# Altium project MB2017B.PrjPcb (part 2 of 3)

## Sheet Power_Stage.SchDoc: Power Stage
size A2; Date: Not used; ApprovedBy: Not used; CheckedBy: Not used; Author: Not used; CompanyName: STMicroelectronics; DrawnBy: Not used; Engineer: Not used; Organization: Not used; Address1: Not used; Address2: Not used; Address3: Not used; Address4: Not used; DocumentNumber: Not used; Revision: Not used; SheetNumber: 3; SheetTotal: 7
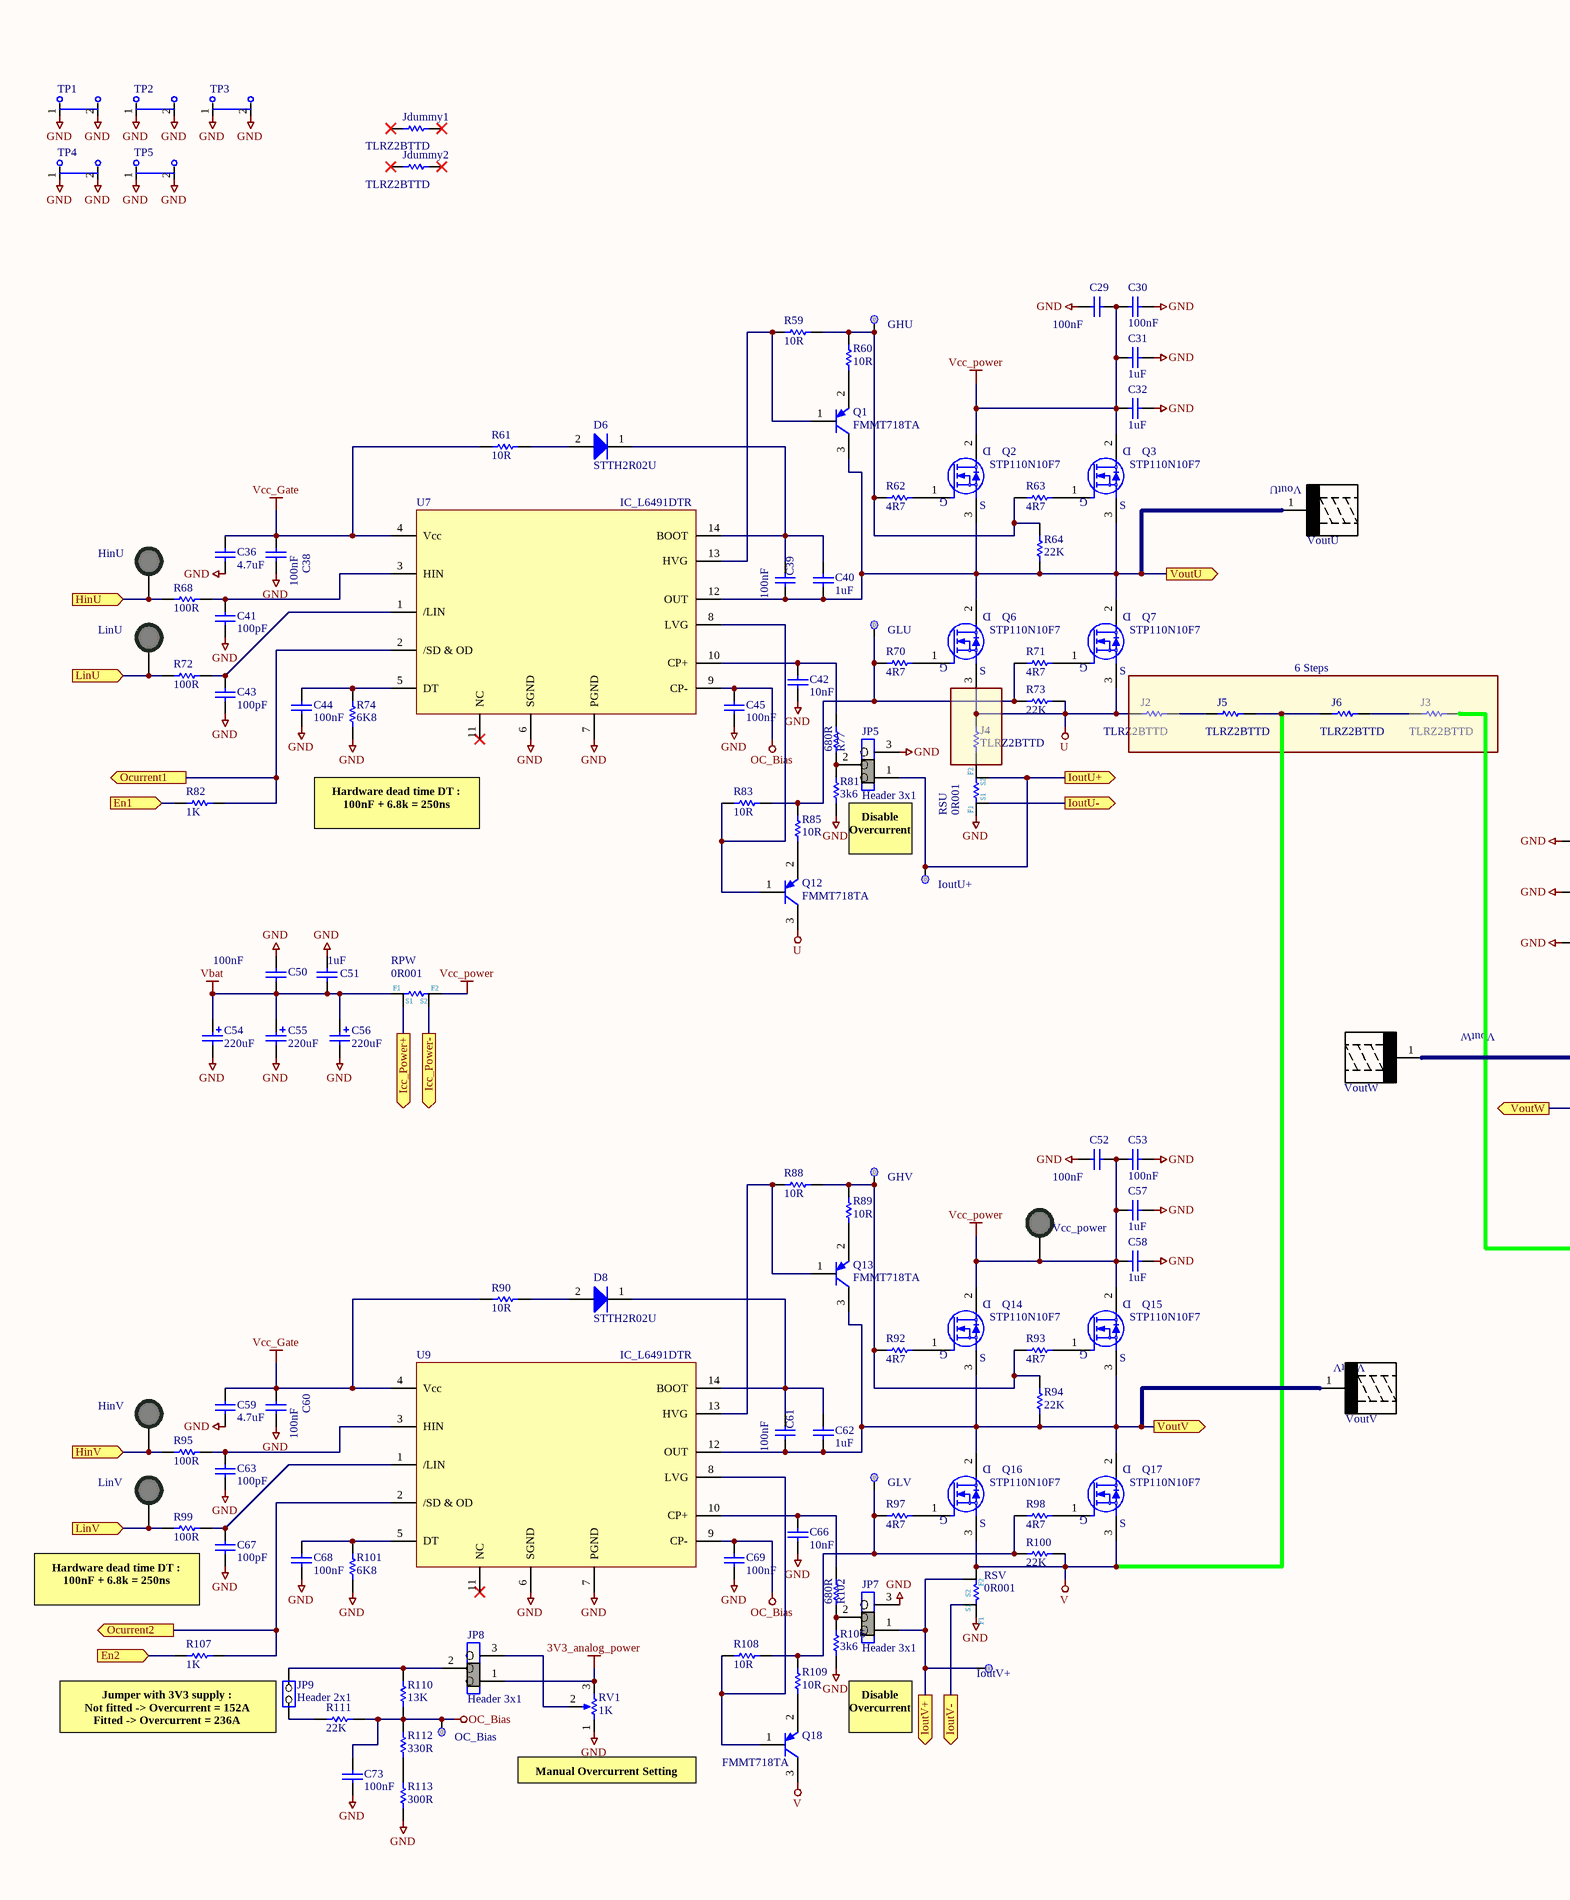
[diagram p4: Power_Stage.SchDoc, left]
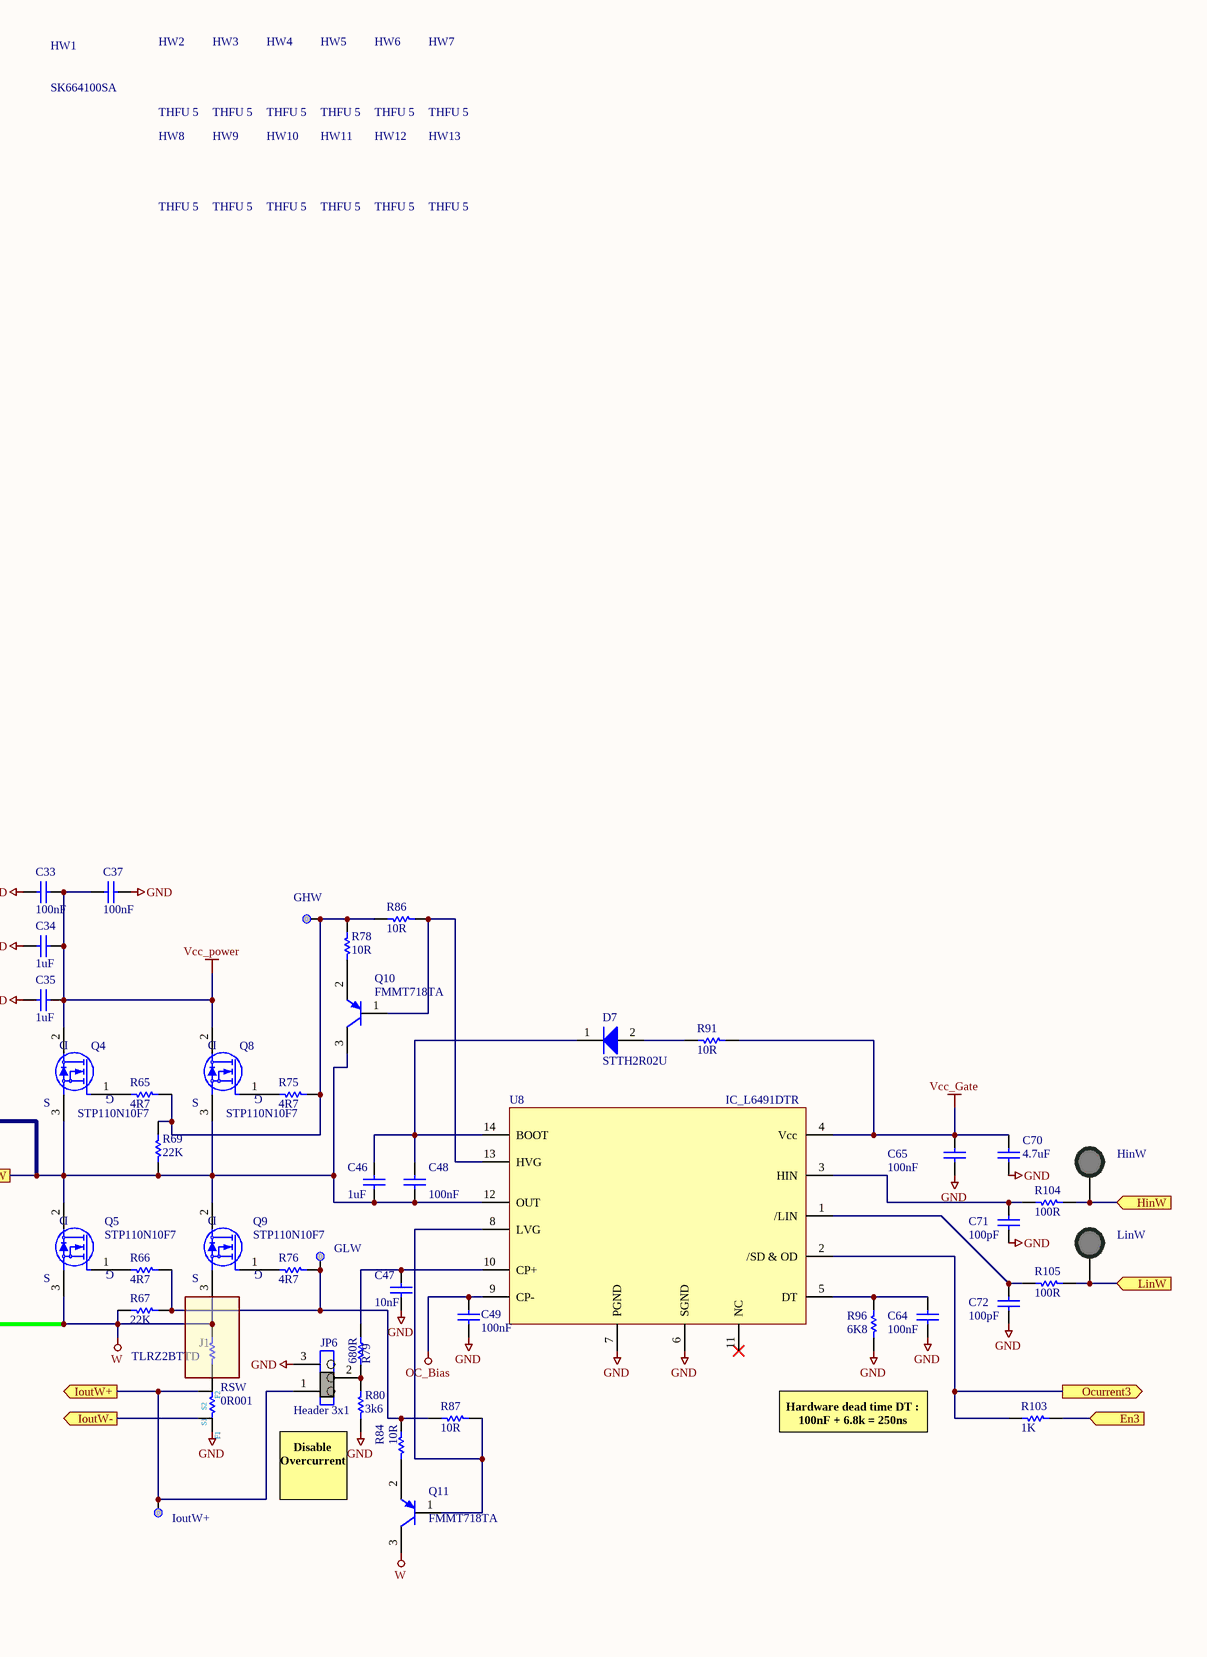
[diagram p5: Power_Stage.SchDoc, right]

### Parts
C29  value 100nF  [C0805]  (hidden comment: Capacitor)
C30  value 100nF  [C0805]  (hidden comment: Capacitor)
C31  value 1uF  [C1206_H1P6]  (hidden comment: Capacitor)
C32  value 1uF  [C1206_H1P6]  (hidden comment: Capacitor)
C33  value 100nF  [C0805]  (hidden comment: Capacitor)
C34  value 1uF  [C1206_H1P6]  (hidden comment: Capacitor)
C35  value 1uF  [C1206_H1P6]  (hidden comment: Capacitor)
C36  value 4.7uF  [C1206_H1P25]  (hidden comment: Capacitor)
C37  value 100nF  [C0805]  (hidden comment: Capacitor)
C38  value 100nF  [C0805_H0P85]  (hidden comment: Capacitor)
C39  value 100nF  [C0805_H0P85]  (hidden comment: Capacitor)
C40  value 1uF  [C1206_H1P15]  (hidden comment: Capacitor)
C41  value 100pF  [C0603_H0P8]  (hidden comment: Capacitor)
C42  value 10nF  [C0603]  (hidden comment: Capacitor)
C43  value 100pF  [C0603_H0P8]  (hidden comment: Capacitor)
C44  value 100nF  [C0603]  (hidden comment: Capacitor)
C45  value 100nF  [C0603]  (hidden comment: Capacitor)
C46  value 1uF  [C1206_H1P15]  (hidden comment: Capacitor)
C47  value 10nF  [C0603]  (hidden comment: Capacitor)
C48  value 100nF  [C0805_H0P85]  (hidden comment: Capacitor)
C49  value 100nF  [C0603]  (hidden comment: Capacitor)
C50  value 100nF  [C0805]  (hidden comment: Capacitor)
C51  value 1uF  [C1206_H1P6]  (hidden comment: Capacitor)
C52  value 100nF  [C0805]  (hidden comment: Capacitor)
C53  value 100nF  [C0805]  (hidden comment: Capacitor)
C54  value 220uF  [CPOL_TDK_B41858C9227M000_H25]  (hidden comment: Cap_POL_TANA)
C55  value 220uF  [CPOL_TDK_B41858C9227M000_H25]  (hidden comment: Cap_POL_TANA)
C56  value 220uF  [CPOL_TDK_B41858C9227M000_H25]  (hidden comment: Cap_POL_TANA)
C57  value 1uF  [C1206_H1P6]  (hidden comment: Capacitor)
C58  value 1uF  [C1206_H1P6]  (hidden comment: Capacitor)
C59  value 4.7uF  [C1206_H1P25]  (hidden comment: Capacitor)
C60  value 100nF  [C0805_H0P85]  (hidden comment: Capacitor)
C61  value 100nF  [C0805_H0P85]  (hidden comment: Capacitor)
C62  value 1uF  [C1206_H1P15]  (hidden comment: Capacitor)
C63  value 100pF  [C0603_H0P8]  (hidden comment: Capacitor)
C64  value 100nF  [C0603]  (hidden comment: Capacitor)
C65  value 100nF  [C0805_H0P85]  (hidden comment: Capacitor)
C66  value 10nF  [C0603]  (hidden comment: Capacitor)
C67  value 100pF  [C0603_H0P8]  (hidden comment: Capacitor)
C68  value 100nF  [C0603]  (hidden comment: Capacitor)
C69  value 100nF  [C0603]  (hidden comment: Capacitor)
C70  value 4.7uF  [C1206_H1P25]  (hidden comment: Capacitor)
C71  value 100pF  [C0603_H0P8]  (hidden comment: Capacitor)
C72  value 100pF  [C0603_H0P8]  (hidden comment: Capacitor)
C73  value 100nF  [C0603]  (hidden comment: Capacitor)
D6  value STTH2R02U  [DIO_SMB_1K_2A]  (hidden comment: DIODE_1K_2A)
D7  value STTH2R02U  [DIO_SMB_1K_2A]  (hidden comment: DIODE_1K_2A)
D8  value STTH2R02U  [DIO_SMB_1K_2A]  (hidden comment: DIODE_1K_2A)
GHU  Test Point  [TP_SMD_1MM]  (value not drawn)  (no BOM)
GHV  Test Point  [TP_SMD_1MM]  (value not drawn)  (no BOM)
GHW  Test Point  [TP_SMD_1MM]  (value not drawn)  (no BOM)
GLU  Test Point  [TP_SMD_1MM]  (value not drawn)  (no BOM)
GLV  Test Point  [TP_SMD_1MM]  (value not drawn)  (no BOM)
GLW  Test Point  [TP_SMD_1MM]  (value not drawn)  (no BOM)
HinU  Test_pin_conn_black - NOT CONNECTED  [TP_PTH-1P02MM_TEST-TERMINAL_RS_101-2391_BLACK]  (value not drawn)
HinV  Test_pin_conn_black - NOT CONNECTED  [TP_PTH-1P02MM_TEST-TERMINAL_RS_101-2391_BLACK]  (value not drawn)
HinW  Test_pin_conn_black - NOT CONNECTED  [TP_PTH-1P02MM_TEST-TERMINAL_RS_101-2391_BLACK]  (value not drawn)
HW1  SK664100SA  [MISC_Fischer_Elektronik_SK664100SA]
HW2  THFU 5
HW3  THFU 5
HW4  THFU 5
HW5  THFU 5
HW6  THFU 5
HW7  THFU 5
HW8  THFU 5
HW9  THFU 5
HW10  THFU 5
HW11  THFU 5
HW12  THFU 5
HW13  THFU 5
IoutU+  Test Point  [TP_SMD_1MM]  (value not drawn)  (no BOM)
IoutV+  Test Point  [TP_SMD_1MM]  (value not drawn)  (no BOM)
IoutW+  Test Point  [TP_SMD_1MM]  (value not drawn)  (no BOM)
J1  value TLRZ2BTTD  [MISC_JUMPER_1206_H0P55]  (hidden comment: Resistor)
J2  value TLRZ2BTTD  [MISC_JUMPER_1206_H0P55]  (hidden comment: Resistor)
J3  value TLRZ2BTTD  [MISC_JUMPER_1206_H0P55]  (hidden comment: Resistor)
J4  value TLRZ2BTTD  [MISC_JUMPER_1206_H0P55]  (hidden comment: Resistor)
J5  value TLRZ2BTTD  [MISC_JUMPER_1206_H0P55]  (hidden comment: Resistor)
J6  value TLRZ2BTTD  [MISC_JUMPER_1206_H0P55]  (hidden comment: Resistor)
Jdummy1  value TLRZ2BTTD  [MISC_JUMPER_1206_H0P55]  (hidden comment: Resistor)
Jdummy2  value TLRZ2BTTD  [MISC_JUMPER_1206_H0P55]  (hidden comment: Resistor)
JP5  value Header 3x1  [CON_SAMTEC_TSW-103-07-F-S]  (hidden comment: Jumper_Header 3x1 Fitted 1-2)
JP6  value Header 3x1  [CON_SAMTEC_TSW-103-07-F-S]  (hidden comment: Jumper_Header 3x1 Fitted 1-2)
JP7  value Header 3x1  [CON_SAMTEC_TSW-103-07-F-S]  (hidden comment: Jumper_Header 3x1 Fitted 1-2)
JP8  value Header 3x1  [CON_SAMTEC_TSW-103-07-F-S]  (hidden comment: Jumper_Header 3x1 Fitted 1-2)
JP9  value Header 2x1  [CON_SAMTEC_TSW-102-07-G-S]  (hidden comment: Jumper_Header 2x1)
LinU  Test_pin_conn_black - NOT CONNECTED  [TP_PTH-1P02MM_TEST-TERMINAL_RS_101-2391_BLACK]  (value not drawn)
LinV  Test_pin_conn_black - NOT CONNECTED  [TP_PTH-1P02MM_TEST-TERMINAL_RS_101-2391_BLACK]  (value not drawn)
LinW  Test_pin_conn_black - NOT CONNECTED  [TP_PTH-1P02MM_TEST-TERMINAL_RS_101-2391_BLACK]  (value not drawn)
OC_Bias  Test Point  [TP_SMD_1MM]  (value not drawn)  (no BOM)
Q1  value FMMT718TA  [PNP_SOT23]  (hidden comment: PNP_SOT23)
Q2  value STP110N10F7  [MOS_TO220-3_VERTICAL_H19P35]  (hidden comment: MOSFET_N-CHANNEL_INV)
Q3  value STP110N10F7  [MOS_TO220-3_VERTICAL_H19P35]  (hidden comment: MOSFET_N-CHANNEL_INV)
Q4  value STP110N10F7  [MOS_TO220-3_VERTICAL_H19P35]  (hidden comment: MOSFET_N-CHANNEL_INV)
Q5  value STP110N10F7  [MOS_TO220-3_VERTICAL_H19P35]  (hidden comment: MOSFET_N-CHANNEL_INV)
Q6  value STP110N10F7  [MOS_TO220-3_VERTICAL_H19P35]  (hidden comment: MOSFET_N-CHANNEL_INV)
Q7  value STP110N10F7  [MOS_TO220-3_VERTICAL_H19P35]  (hidden comment: MOSFET_N-CHANNEL_INV)
Q8  value STP110N10F7  [MOS_TO220-3_VERTICAL_H19P35]  (hidden comment: MOSFET_N-CHANNEL_INV)
Q9  value STP110N10F7  [MOS_TO220-3_VERTICAL_H19P35]  (hidden comment: MOSFET_N-CHANNEL_INV)
Q10  value FMMT718TA  [PNP_SOT23]  (hidden comment: PNP_SOT23)
Q11  value FMMT718TA  [PNP_SOT23]  (hidden comment: PNP_SOT23)
Q12  value FMMT718TA  [PNP_SOT23]  (hidden comment: PNP_SOT23)
Q13  value FMMT718TA  [PNP_SOT23]  (hidden comment: PNP_SOT23)
Q14  value STP110N10F7  [MOS_TO220-3_VERTICAL_H19P35]  (hidden comment: MOSFET_N-CHANNEL_INV)
Q15  value STP110N10F7  [MOS_TO220-3_VERTICAL_H19P35]  (hidden comment: MOSFET_N-CHANNEL_INV)
Q16  value STP110N10F7  [MOS_TO220-3_VERTICAL_H19P35]  (hidden comment: MOSFET_N-CHANNEL_INV)
Q17  value STP110N10F7  [MOS_TO220-3_VERTICAL_H19P35]  (hidden comment: MOSFET_N-CHANNEL_INV)
Q18  value FMMT718TA  [PNP_SOT23]  (hidden comment: PNP_SOT23)
R59  value 10R  [R0805]  (hidden comment: Resistor)
R60  value 10R  [R0805]  (hidden comment: Resistor)
R61  value 10R  [R0805]  (hidden comment: Resistor)
R62  value 4R7  [R0805_H0P6]  (hidden comment: Resistor)
R63  value 4R7  [R0805_H0P6]  (hidden comment: Resistor)
R64  value 22K  [R0805_H0P5]  (hidden comment: Resistor)
R65  value 4R7  [R0805_H0P6]  (hidden comment: Resistor)
R66  value 4R7  [R0805_H0P6]  (hidden comment: Resistor)
R67  value 22K  [R0805_H0P5]  (hidden comment: Resistor)
R68  value 100R  [R0603]  (hidden comment: Resistor)
R69  value 22K  [R0805_H0P5]  (hidden comment: Resistor)
R70  value 4R7  [R0805_H0P6]  (hidden comment: Resistor)
R71  value 4R7  [R0805_H0P6]  (hidden comment: Resistor)
R72  value 100R  [R0603]  (hidden comment: Resistor)
R73  value 22K  [R0805_H0P5]  (hidden comment: Resistor)
R74  value 6K8  [R0603]  (hidden comment: Resistor)
R75  value 4R7  [R0805_H0P6]  (hidden comment: Resistor)
R76  value 4R7  [R0805_H0P6]  (hidden comment: Resistor)
R77  value 680R  [R0603]  (hidden comment: Resistor)
R78  value 10R  [R0805]  (hidden comment: Resistor)
R79  value 680R  [R0603]  (hidden comment: Resistor)
R80  value 3k6  [R0603_H0P45]  (hidden comment: Resistor)
R81  value 3k6  [R0603_H0P45]  (hidden comment: Resistor)
R82  value 1K  [R0603]  (hidden comment: Resistor)
R83  value 10R  [R0805]  (hidden comment: Resistor)
R84  value 10R  [R0805]  (hidden comment: Resistor)
R85  value 10R  [R0805]  (hidden comment: Resistor)
R86  value 10R  [R0805]  (hidden comment: Resistor)
R87  value 10R  [R0805]  (hidden comment: Resistor)
R88  value 10R  [R0805]  (hidden comment: Resistor)
R89  value 10R  [R0805]  (hidden comment: Resistor)
R90  value 10R  [R0805]  (hidden comment: Resistor)
R91  value 10R  [R0805]  (hidden comment: Resistor)
R92  value 4R7  [R0805_H0P6]  (hidden comment: Resistor)
R93  value 4R7  [R0805_H0P6]  (hidden comment: Resistor)
R94  value 22K  [R0805_H0P5]  (hidden comment: Resistor)
R95  value 100R  [R0603]  (hidden comment: Resistor)
R96  value 6K8  [R0603]  (hidden comment: Resistor)
R97  value 4R7  [R0805_H0P6]  (hidden comment: Resistor)
R98  value 4R7  [R0805_H0P6]  (hidden comment: Resistor)
R99  value 100R  [R0603]  (hidden comment: Resistor)
R100  value 22K  [R0805_H0P5]  (hidden comment: Resistor)
R101  value 6K8  [R0603]  (hidden comment: Resistor)
R102  value 680R  [R0603]  (hidden comment: Resistor)
R103  value 1K  [R0603]  (hidden comment: Resistor)
R104  value 100R  [R0603]  (hidden comment: Resistor)
R105  value 100R  [R0603]  (hidden comment: Resistor)
R106  value 3k6  [R0603_H0P45]  (hidden comment: Resistor)
R107  value 1K  [R0603]  (hidden comment: Resistor)
R108  value 10R  [R0805]  (hidden comment: Resistor)
R109  value 10R  [R0805]  (hidden comment: Resistor)
R110  value 13K  [R0603]  (hidden comment: Resistor)
R111  value 22K  [R0603]  (hidden comment: Resistor)
R112  value 330R  [R0603]  (hidden comment: Resistor)
R113  value 300R  [R0603]  (hidden comment: Resistor)
RPW  value 0R001  [R4026_APR_CSM4026Y_Y14780R00100F9R]  (hidden comment: RES_CSM4026Y)
RSU  value 0R001  [R4026_APR_CSM4026Y_Y14780R00100F9R]  (hidden comment: RES_CSM4026Y)
RSV  value 0R001  [R4026_APR_CSM4026Y_Y14780R00100F9R]  (hidden comment: RES_CSM4026Y)
RSW  value 0R001  [R4026_APR_CSM4026Y_Y14780R00100F9R]  (hidden comment: RES_CSM4026Y)
RV1  value 1K  [POT_BOURNS_3386P-1-101TLF]  (hidden comment: POTENTIOMETER)
TP1  Test_pinX2  [CON_JUMPER_HARWIN_S1621-46R]  (value not drawn)
TP2  Test_pinX2  [CON_JUMPER_HARWIN_S1621-46R]  (value not drawn)
TP3  Test_pinX2  [CON_JUMPER_HARWIN_S1621-46R]  (value not drawn)
TP4  Test_pinX2  [CON_JUMPER_HARWIN_S1621-46R]  (value not drawn)
TP5  Test_pinX2  [CON_JUMPER_HARWIN_S1621-46R]  (value not drawn)
U7  IC_L6491DTR  [ICC_SO14_8P75X6P20_P127_H1P75]
U8  IC_L6491DTR  [ICC_SO14_8P75X6P20_P127_H1P75]
U9  IC_L6491DTR  [ICC_SO14_8P75X6P20_P127_H1P75]
Vcc_power  Test_pin_conn_black - NOT CONNECTED  [TP_PTH-1P02MM_TEST-TERMINAL_RS_101-2391_BLACK]  (value not drawn)
VoutU  CON_M4_SNAP_IN_THR_KEYSTONE_7798  [CON_KEYSTONE_M4-SNAP_7798]  (value not drawn)
VoutV  CON_M4_SNAP_IN_THR_KEYSTONE_7798  [CON_KEYSTONE_M4-SNAP_7798]  (value not drawn)
VoutW  CON_M4_SNAP_IN_THR_KEYSTONE_7798  [CON_KEYSTONE_M4-SNAP_7798]  (value not drawn)

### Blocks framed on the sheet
6 Steps: J2 J3 J5 J6

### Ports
En1 (in), En2 (in), En3 (in), HinU (in), HinV (in), HinW (in), Icc_Power+ (out), Icc_Power- (out), IoutU+ (out), IoutU- (out), IoutV+ (out), IoutV- (out), IoutW+ (out), IoutW- (out), LinU (in), LinV (in), LinW (in), Ocurrent1 (out), Ocurrent2 (out), Ocurrent3 (out), VoutU (out), VoutV (out), VoutW (out)

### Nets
3V3_analog_power: JP8.1 RV1.3(TOP)
GND: C29.2 C30.2 C31.2 C32.2 C33.2 C34.2 C35.2 C36.1 C37.2 C38.1 C41.1 C42.2 C43.1 C44.1 C45.1 C47.2 C49.1 C50.2 C51.2 C52.2 C53.2 C54.2 C55.2 C56.2 C57.2 C58.2 C59.1 C60.1 C63.1 C64.1 C65.1 C66.2 C67.1 C68.1 C69.1 C70.1 C71.1 C72.1 C73.1 JP5.3 JP6.3 JP7.3 R74.1 R80.1 R81.1 R96.2 R101.1 R106.1 R113.1 RSU.F1 RSV.F1 RSW.F1 RV1.1(BOT) TP1.1 TP1.2 TP2.1 TP2.2 TP3.1 TP3.2 TP4.1 TP4.2 TP5.1 TP5.2 U7.6(SGND) U7.7(PGND) U8.6(SGND) U8.7(PGND) U9.6(SGND) U9.7(PGND)
OC_Bias: C45.2 C49.2 C69.2 C73.2 OC_Bias.1 R110.1 R111.2 R112.2 U7.9(CP-) U8.9(CP-) U9.9(CP-)
U: J2.2 J4.2 Q6.3(S) Q7.3(S) Q12.3(C) R73.2
V: J5.2 J6.2 Q16.3(S) Q17.3(S) Q18.3(C) R100.2 RSV.F2
Vbat: C50.1 C51.1 C54.1 C55.1 C56.1 RPW.F1
Vcc_Gate: C36.2 C38.2 C59.2 C60.2 C65.2 C70.2 R61.1 R90.1 R91.1 U7.4(Vcc) U8.4(Vcc) U9.4(Vcc)
Vcc_power: C29.1 C30.1 C31.1 C32.1 C33.1 C34.1 C35.1 C37.1 C52.1 C53.1 C57.1 C58.1 Q2.2(D) Q3.2(D) Q4.2(D) Q8.2(D) Q14.2(D) Q15.2(D) RPW.F2 Vcc_power.1
W: J1.2 J3.1 Q5.3(S) Q9.3(S) Q11.3(C) R67.2
En1: R82.1 ; port En1
En2: R107.1 ; port En2
En3: R103.1 ; port En3
HinU: HinU.1 R68.2 ; port HinU
HinV: HinV.1 R95.2 ; port HinV
HinW: HinW.1 R104.2 ; port HinW
Icc_Power+: RPW.S1 ; port Icc_Power+
Icc_Power-: RPW.S2 ; port Icc_Power-
IoutU+: IoutU+.1 JP5.1 RSU.S2 ; port IoutU+
IoutU-: RSU.S1 ; port IoutU-
IoutV+: IoutV+.1 JP7.1 RSV.S2 ; port IoutV+
IoutV-: RSV.S1 ; port IoutV-
IoutW+: IoutW+.1 JP6.1 RSW.S2 ; port IoutW+
IoutW-: RSW.S1 ; port IoutW-
LinU: LinU.1 R72.2 ; port LinU
LinV: LinV.1 R99.2 ; port LinV
LinW: LinW.1 R105.2 ; port LinW
Ocurrent1: R82.2 U7.2(/SD_&_OD) ; port Ocurrent1
Ocurrent2: R107.2 U9.2(/SD_&_OD) ; port Ocurrent2
Ocurrent3: R103.2 U8.2(/SD_&_OD) ; port Ocurrent3
VoutU: C39.1 C40.1 Q1.3(C) Q2.3(S) Q3.3(S) Q6.2(D) Q7.2(D) R64.1 U7.12(OUT) VoutU.1 ; port VoutU
VoutV: C61.1 C62.1 Q13.3(C) Q14.3(S) Q15.3(S) Q16.2(D) Q17.2(D) R94.1 U9.12(OUT) VoutV.1 ; port VoutV
VoutW: C46.1 C48.1 Q4.3(S) Q5.2(D) Q8.3(S) Q9.2(D) Q10.3(C) R69.2 U8.12(OUT) VoutW.1 ; port VoutW
NetC39_2: C39.2 C40.2 D6.1(K) U7.14(BOOT)
NetC41_2: C41.2 R68.1 U7.3(HIN)
NetC42_1: C42.1 R77.2 U7.10(CP+)
NetC43_2: C43.2 R72.1 U7.1(/LIN)
NetC44_2: C44.2 R74.2 U7.5(DT)
NetC46_2: C46.2 C48.2 D7.1(K) U8.14(BOOT)
NetC47_1: C47.1 R79.2 U8.10(CP+)
NetC61_2: C61.2 C62.2 D8.1(K) U9.14(BOOT)
NetC63_2: C63.2 R95.1 U9.3(HIN)
NetC64_2: C64.2 R96.1 U8.5(DT)
NetC66_1: C66.1 R102.2 U9.10(CP+)
NetC67_2: C67.2 R99.1 U9.1(/LIN)
NetC68_2: C68.2 R101.2 U9.5(DT)
NetC71_2: C71.2 R104.1 U8.3(HIN)
NetC72_2: C72.2 R105.1 U8.1(/LIN)
NetD6_2: D6.2(A) R61.2
NetD7_2: D7.2(A) R91.2
NetD8_2: D8.2(A) R90.2
NetGHU_1: GHU.1 R59.2 R60.2 R62.1 R63.1 R64.2
NetGHV_1: GHV.1 R88.2 R89.2 R92.1 R93.1 R94.2
NetGHW_1: GHW.1 R65.1 R69.1 R75.1 R78.2 R86.2
NetGLU_1: GLU.1 R70.1 R71.1 R73.1 R83.2 R85.2
NetGLV_1: GLV.1 R97.1 R98.1 R100.1 R108.2 R109.2
NetGLW_1: GLW.1 R66.1 R67.1 R76.1 R84.2 R87.2
NetJ1_1: J1.1 RSW.F2
NetJ2_1: J2.1 J5.1
NetJ3_2: J3.2 J6.1
NetJ4_1: J4.1 RSU.F2
NetJP5_2: JP5.2 R77.1 R81.2
NetJP6_2: JP6.2 R79.1 R80.2
NetJP7_2: JP7.2 R102.1 R106.2
NetJP8_2: JP8.2 JP9.1(COMMON) R110.2
NetJP8_3: JP8.3 RV1.2(TAP)
NetJP9_2: JP9.2(NO) R111.1
NetQ1_1: Q1.1(B) R59.1 U7.13(HVG)
NetQ1_2: Q1.2(E) R60.1
NetQ2_1: Q2.1(G) R62.2
NetQ3_1: Q3.1(G) R63.2
NetQ4_1: Q4.1(G) R65.2
NetQ5_1: Q5.1(G) R66.2
NetQ6_1: Q6.1(G) R70.2
NetQ7_1: Q7.1(G) R71.2
NetQ8_1: Q8.1(G) R75.2
NetQ9_1: Q9.1(G) R76.2
NetQ10_1: Q10.1(B) R86.1 U8.13(HVG)
NetQ10_2: Q10.2(E) R78.1
NetQ11_1: Q11.1(B) R87.1 U8.8(LVG)
NetQ11_2: Q11.2(E) R84.1
NetQ12_1: Q12.1(B) R83.1 U7.8(LVG)
NetQ12_2: Q12.2(E) R85.1
NetQ13_1: Q13.1(B) R88.1 U9.13(HVG)
NetQ13_2: Q13.2(E) R89.1
NetQ14_1: Q14.1(G) R92.2
NetQ15_1: Q15.1(G) R93.2
NetQ16_1: Q16.1(G) R97.2
NetQ17_1: Q17.1(G) R98.2
NetQ18_1: Q18.1(B) R108.1 U9.8(LVG)
NetQ18_2: Q18.2(E) R109.1
NetR112_1: R112.1 R113.2

Not connected (* = marked no-connect by the designer): Jdummy1 1* 2*; Jdummy2 1* 2*; U7 11(NC)*; U8 11(NC)*; U9 11(NC)*

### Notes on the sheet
- (near VoutU) VoutU
- Hardware dead time DT :
  100nF + 6.8k = 250ns
- (near R81) Disable
  Overcurrent
- (near VoutW) VoutW
- (near VoutV) VoutV
- (near R80) Disable
  Overcurrent
- (near JP9) Jumper with 3V3 supply :
  Not fitted -> Overcurrent = 152A
  Fitted -> Overcurrent = 236A
- (near RV1) Manual Overcurrent Setting
- (near R106) Disable
  Overcurrent

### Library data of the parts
C29 C30 C33 C37 C50 C52 C53 = MCD-01093: Capacitor, MLCC, 100nF, 100V, X7R, +/-10%, 0805, T=1.25mm; Part_Preference: Recommended; Manufacturer: TDK; Manufacturer_Part_Number: C2012X7R2A104K125AA; Order_Code_RS: 921-4157; Component_Country_Of_Origin: Unknown; ShowFields: YES; ID: 3402
C31 C32 C34 C35 C51 C57 C58 = MCD-03394: Capacitor, MLCC, 1uF, 100V, X7R, 10%, 1206, T=1.6mm; Part_Preference: Recommended; Manufacturer: TDK; Manufacturer_Part_Number: C3216X7R2A105K160AA; Order_Code_RS: 242-7428; ShowFields: YES; ID: 5510; Component_Country_Of_Origin: Japan°
C36 C59 C70 = MCD-00013: Capacitor, MLCC, 4.7uF, 50V, X7R, +/-10%, 1206, T=1.27mm; Part_Preference: Recommended; Manufacturer: AVX; Manufacturer_Part_Number: 12065C475KAT2A; Order_Code_RS: 1908177; Component_Country_Of_Origin: China, Malaysia; ShowFields: YES; ID: 2466
C38 C39 C48 C60 C61 C65 = MCD-01525: Capacitor, MLCC, 100nF, 50V, X7R, +/-10%, 0805, T=0.85mm; BMS_Part_Number: 9142249; Part_Preference: Recommended; Manufacturer: YAGEO; Manufacturer_Part_Number: CC0805KRX7R9BB104; Order_Code_RS: 669-8842; Component_Country_Of_Origin: China; ShowFields: YES; ID: 3625
C40 C46 C62 = MCD-00609: Capacitor, MLCC, 1uF, 50V, X7R, +/-10%, 1206, T=1.15mm; Part_Preference: Forbidden; Manufacturer: MURATA; Manufacturer_Part_Number: GRM31MR71H105KA88L; Order_Code_RS: 790-0623; ShowFields: YES; ID: 3135
C41 C43 C63 C67 C71 C72 = MCD-01648: Capacitor, MLCC, 100pF, 50V, NPO, +/-5%, 0603, T=0.8mm; Part_Preference: Recommended; Manufacturer: YAGEO; Manufacturer_Part_Number: CC0603JRNPO9BN101; Order_Code_RS: 625-0267; Component_Country_Of_Origin: China; ShowFields: YES; ID: 3748
C42 C47 C66 = MCD-01102: Capacitor, MLCC, 10nF, 50V ,X7R, +/-10%, 0603, T=0.8mm; Part_Preference: Not recommended; Manufacturer: YAGEO; Manufacturer_Part_Number: CC0603KRX7R9BB103; Order_Code_RS: 616-9537; Component_Country_Of_Origin: China; ShowFields: YES; ID: 3392
C44 C45 C49 C64 C68 C69 C73 = MCD-01099: Capacitor, MLCC, 100nF, 50V, X7R, +/-10%, 0603, T=0.8mm; BMS_Part_Number: 9142278; Part_Preference: Recommended; Manufacturer: YAGEO; Manufacturer_Part_Number: CC0603KRX7R9BB104; Order_Code_RS: 669-8767; Component_Country_Of_Origin: China; ShowFields: YES; ID: 3397
C54-C56 = MCD-03694: Capacitor, Aluminum Electrolytic Low ESR, 220uF, 100V, 0.099Ohms, +/-20%, 16x25mm, T=25mm; Part_Preference: Recommended; Manufacturer: TDK; Manufacturer_Part_Number: B41858C9227M000; Order_Code_RS: 261-0666; ShowFields: YES; ID: 5810; Component_Country_Of_Origin: China°
D6-D8 = MCD-03397: Diode, Ultrafast Recovery Rectifier, 0V89, 2A, 200V, DO-214AA; Part_Preference: Forbidden; Manufacturer: STMICROELECTRONICS; Order_Code_RS: 249-707; ShowFields: YES; ID: 5513; Component_Country_Of_Origin: China
GHU GHV GHW GLU GLV GLW IoutU+ IoutV+ IoutW+ OC_Bias = MCD-00074: Test Point 1mm; Part_Type: Misc; Part_Preference: Recommended; ShowFields: YES; ID: 2518; Component_Country_Of_Origin: Unknown
HinU HinV HinW LinU LinV LinW Vcc_power = MCD-00713: Black test terminal, Hole diameter=1.02mm; Part_Type: Misc; Part_Preference: Recommended; Manufacturer: VERO; Value: 20-2137; Order_Code_RS: 101-2391; Component_Country_Of_Origin: UK; ShowFields: YES; ID: 3032
HW1 = MISC_HEATSINK_Fischer_Elektronik_SK664100SA: Manufacturer_1: Fischer Elektronik
HW2-HW13 = MISC_CLIP_HEATSINK_Fischer_Elektronik_THFU5: Manufacturer_1: FISHER ELEKTRONIK
J1-J6 Jdummy1 Jdummy2 = MCD-03351: Jumper, 1206, 50A, 200uR; Part_Type: Misc; Part_Preference: Recommended; Manufacturer: KOA; Order_Code_RS: 178-6589; Component_Country_Of_Origin: Japan°; ShowFields: YES; ID: 5467
JP5-JP8 = MCD-01905: Header, 3x1, 2.54mm, VR, TH, T=5.84mm/2.54mm; Part_Type: Connector; Part_Preference: Recommended; Manufacturer: SAMTEC; Manufacturer_Part_Number: TSW-103-07-G-S; Order_Code_RS: 161-2521; Component_Country_Of_Origin: China, Costa Rica, Malaysia, USA, Vietnam; ShowFields: YES; ID: 4005
JP9 = MCD-00045: Header, 2x1, 2.54mm, VR, TH, T=5.84mm/2.54mm; Part_Type: Connector; Part_Preference: Recommended; Manufacturer: SAMTEC; Manufacturer_Part_Number: TSW-102-07-G-S; Full_Alternate_Internal_Part_Number: MCD-02390; Partial_Alternate_Internal_Part_Number: MCD-02957, MCD-03720; Order_Code_RS: 2505044; Component_Country_Of_Origin: China, Costa Rica, Malaysia, USA, Vietnam; ShowFields: YES; ID: 2545
Q1 Q10-Q13 Q18 = MCD-03327: Transistor, PNP, 20V, 1.5A, SOT-23; Part_Preference: Recommended; Manufacturer: DIODES INCORPORATED; Order_Code_RS: 154-873P; Component_Country_Of_Origin: China°°; ShowFields: YES; ID: 5443
Q2-Q9 Q14-Q17 = MCD-03382: Transistor, MOSFET, N-CH, 100V, 110A, TO-220; Part_Preference: Recommended; Manufacturer: STMICROELECTRONICS; Order_Code_RS: 786-3776; ShowFields: YES; ID: 5498; Component_Country_Of_Origin: China
R59-R61 R78 R83-R91 R108 R109 = MCD-01111: Resistor, 10R, 0805, +/-1%, 1/4W; Part_Preference: Recommended; Manufacturer: STACKPOLE; Manufacturer_Part_Number: RNCP0805FTD10R0; Component_Country_Of_Origin: Taiwan°; ShowFields: YES; ID: 3385
R62 R63 R65 R66 R70 R71 R75 R76 R92 R93 R97 R98 = MCD-03477: Resistor, 4R7, 0805, +/-1%, 1/8W; Part_Preference: Recommended; Manufacturer: YAGEO; Manufacturer_Part_Number: RC0805FR-074R7L; Order_Code_RS: 9237208; Component_Country_Of_Origin: China; ShowFields: YES; ID: 5593
R64 R67 R69 R73 R94 R100 = MCD-03667: Resistor, 22K, 0805, +/-1%, 1/8W; Part_Preference: Recommended; Manufacturer: YAGEO; Manufacturer_Part_Number: RC0805FR-0722KL; Order_Code_RS: 199-5687; Component_Country_Of_Origin: China; ShowFields: YES; ID: 5783
R68 R72 R95 R99 R104 R105 = MCD-00224: Resistor, 100R, 0603, +/-1%, 1/10W; Part_Preference: Recommended; Manufacturer: YAGEO; Manufacturer_Part_Number: RC0603FR-07100RL; Component_Country_Of_Origin: China; ShowFields: YES; ID: 2643
R74 R96 R101 = MCD-00510: Resistor, 6K8, 0603, +/-1%, 1/10W; Part_Preference: Recommended; Manufacturer: YAGEO; Manufacturer_Part_Number: RC0603FR-076K8L; Component_Country_Of_Origin: China; ShowFields: YES; ID: 3230
R77 R79 R102 = MCD-00508: Resistor, 680R, 0603, +/-1%, 1/10W; Part_Preference: Recommended; Manufacturer: YAGEO; Manufacturer_Part_Number: RC0603FR-07680RL; Component_Country_Of_Origin: China; ShowFields: YES; ID: 3235
R80 R81 R106 = MCD-03337: Resistor, 3K6, 0603, +/-1%, 1/10W; Part_Preference: Recommended; Manufacturer: PANASONIC; Manufacturer_Part_Number: ERJ3EKF3601V; Component_Country_Of_Origin: China°; ShowFields: YES; ID: 5453
R82 R103 R107 = MCD-00070: Resistor, 1K, 0603, +/-1%, 1/10W; Part_Preference: Recommended; Manufacturer: YAGEO; Manufacturer_Part_Number: RC0603FR-071KL; Order_Code_RS: 9238484RL; Component_Country_Of_Origin: China; ShowFields: YES; ID: 2522
R110 = MCD-00384: Resistor, 13K, 0603,+/-1%, 1/10W; Part_Preference: Recommended; Manufacturer: YAGEO; Manufacturer_Part_Number: RC0603FR-0713KL; Component_Country_Of_Origin: China; ShowFields: YES; ID: 2894
R111 = MCD-00430: Resistor, 22K, 0603, +/-1%, 1/10W; Part_Preference: Recommended; Manufacturer: YAGEO; Manufacturer_Part_Number: RC0603FR-0722KL; Component_Country_Of_Origin: China; ShowFields: YES; ID: 2847
R112 = MCD-00197: Resistor, 330R, 0603, +/-1%, 1/10W; BMS_Part_Number: 9129729; Part_Preference: Recommended; Manufacturer: YAGEO; Manufacturer_Part_Number: RC0603FR-07330RL; Component_Country_Of_Origin: China; ShowFields: YES; ID: 2672
R113 = MCD-00450: Resistor, 300R, 0603, +/-1%, 1/10W; Part_Preference: Recommended; Manufacturer: YAGEO; Manufacturer_Part_Number: RC0603FR-07300RL; Component_Country_Of_Origin: China; ShowFields: YES; ID: 2828
RPW RSU RSV RSW = MCD-03392: Resistor, 0R001, 4026, 1%, 5W, Power Shunt Resistor with Senses, 129A; Part_Preference: Not recommended; Manufacturer: VISHAY; Manufacturer_Part_Number: Y14780R00100F9R; Component_Country_Of_Origin: Israel°; ShowFields: YES; ID: 5508
RV1 = MCD-02050: Trimmer, 1k, 3386p, +/-10%, 1/2W, T=4.83mm; Part_Type: Resistor; Part_Preference: Recommended; Manufacturer: BOURNS; Manufacturer_Part_Number: 3386P-1-102TLF; Component_Country_Of_Origin: Costa Rica; ShowFields: YES; ID: 4150
TP1-TP5 = MCD-03485: Test Point SMD H:1.8mm, L:10.16mm, l:1.8mm; Part_Type: Misc; Part_Preference: Recommended; Manufacturer: HARWIN; Value: S1621-46R; Order_Code_RS: 2751488; Component_Country_Of_Origin: UK; ShowFields: YES; ID: 5601
U7-U9 = MCD-03383: Gate Driver, High Voltage, High and Low-side, 4A; Part_Type: IC; Part_Preference: Not recommended; Manufacturer: STMICROELECTRONICS; Order_code_RS: 188-8518; Component_Country_Of_Origin: Morocco; ShowFields: YES; ID: 5499
VoutU VoutV VoutW = MCD-03715: Connector, M4, SNAP IN, 1x1, VR, TH, T=11.68mm; Part_Preference: Not recommended; Manufacturer: KEYSTONE ELECTRONICS; Manufacturer_Part_Number: 7798; Value: TERM SCREW M4 PCB 30A; ShowFields: YES; ID: 5831; Component_Country_Of_Origin: Unknown

## Sheet Sensors.SchDoc: Sensors
size A3; Date: Not used; ApprovedBy: Not used; CheckedBy: Not used; Author: Not used; CompanyName: STMicroelectronics; DrawnBy: Not used; Engineer: Not used; Organization: Not used; Address1: Not used; Address2: Not used; Address3: Not used; Address4: Not used; DocumentNumber: Not used; Revision: Not used; SheetNumber: 5; SheetTotal: 7
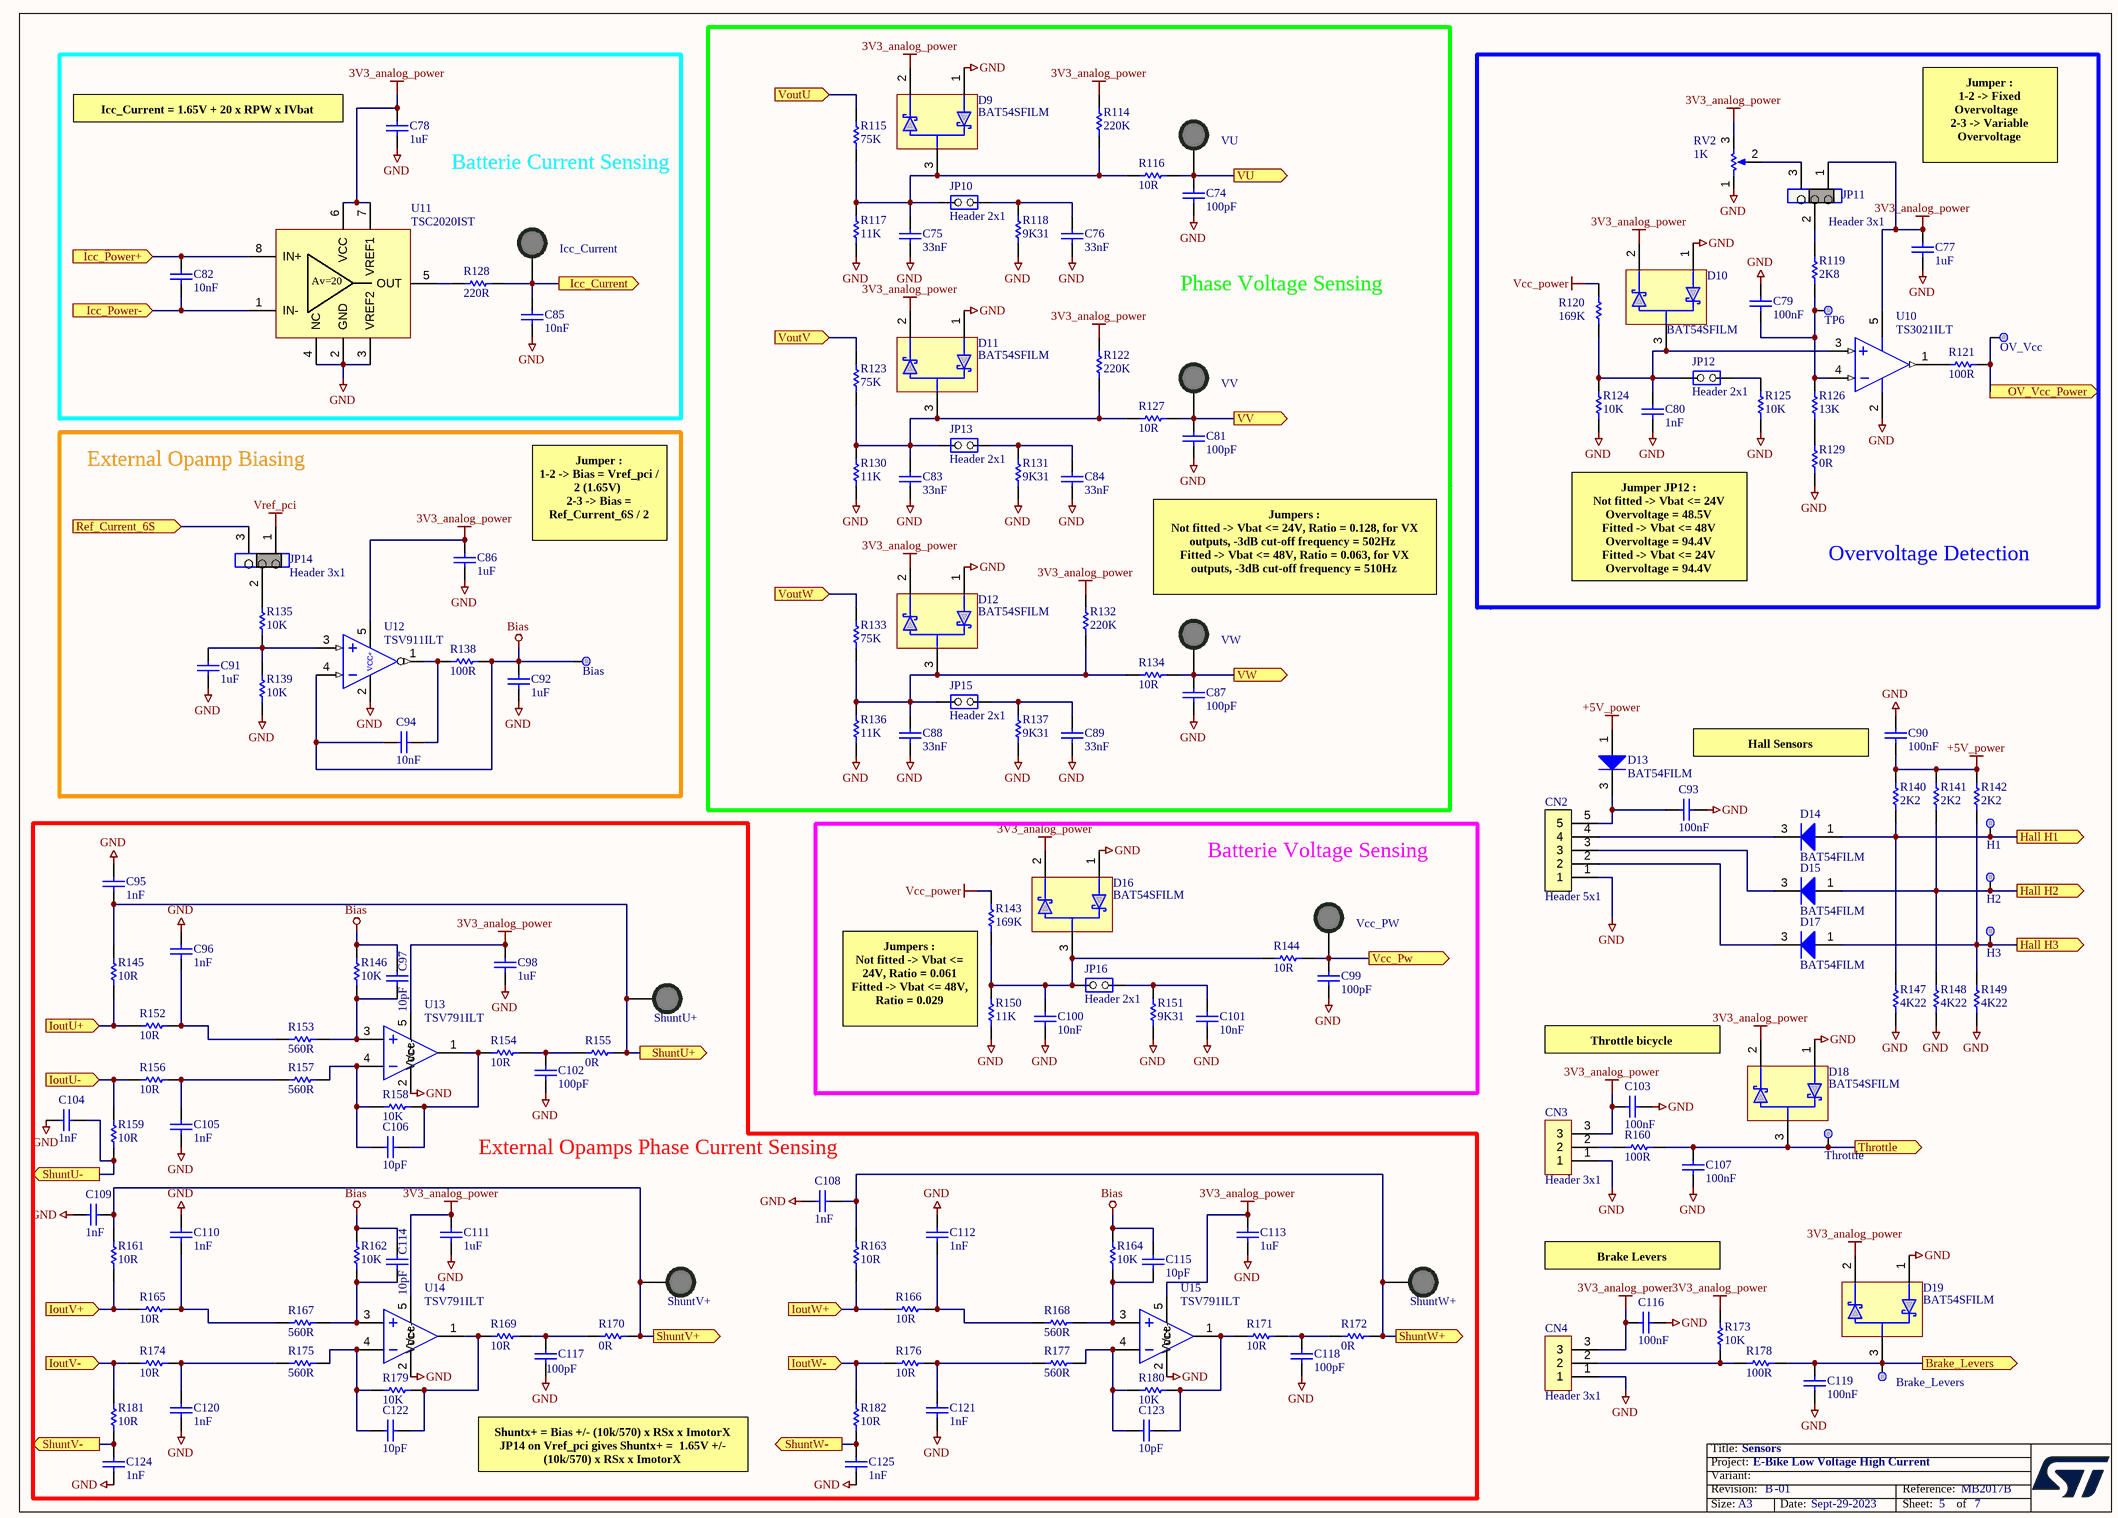
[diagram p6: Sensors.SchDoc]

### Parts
Bias  Test Point  [TP_SMD_1MM]  (value not drawn)  (no BOM)
Brake_Levers  Test Point  [TP_SMD_1MM]  (value not drawn)  (no BOM)
C74  value 100pF  [C0603]  (hidden comment: Capacitor)
C75  value 33nF  [C0603]  (hidden comment: Capacitor)
C76  value 33nF  [C0603]  (hidden comment: Capacitor)
C77  value 1uF  [C0805_H0P85]  (hidden comment: Capacitor)
C78  value 1uF  [C0805_H0P85]  (hidden comment: Capacitor)
C79  value 100nF  [C0603]  (hidden comment: Capacitor)
C80  value 1nF  [C0603]  (hidden comment: Capacitor)
C81  value 100pF  [C0603]  (hidden comment: Capacitor)
C82  value 10nF  [C0603]  (hidden comment: Capacitor)
C83  value 33nF  [C0603]  (hidden comment: Capacitor)
C84  value 33nF  [C0603]  (hidden comment: Capacitor)
C85  value 10nF  [C0603]  (hidden comment: Capacitor)
C86  value 1uF  [C0805_H0P85]  (hidden comment: Capacitor)
C87  value 100pF  [C0603]  (hidden comment: Capacitor)
C88  value 33nF  [C0603]  (hidden comment: Capacitor)
C89  value 33nF  [C0603]  (hidden comment: Capacitor)
C90  value 100nF  [C0603]  (hidden comment: Capacitor)
C91  value 1uF  [C0805_H0P85]  (hidden comment: Capacitor)
C92  value 1uF  [C0805_H0P85]  (hidden comment: Capacitor)
C93  value 100nF  [C0603]  (hidden comment: Capacitor)
C94  value 10nF  [C0603]  (hidden comment: Capacitor)
C95  value 1nF  [C0603]  (hidden comment: Capacitor)
C96  value 1nF  [C0603]  (hidden comment: Capacitor)
C97  value 10pF  [C0603]  (hidden comment: Capacitor)
C98  value 1uF  [C0805_H0P85]  (hidden comment: Capacitor)
C99  value 100pF  [C0603]  (hidden comment: Capacitor)
C100  value 10nF  [C0603]  (hidden comment: Capacitor)
C101  value 10nF  [C0603]  (hidden comment: Capacitor)
C102  value 100pF  [C0603]  (hidden comment: Capacitor)
C103  value 100nF  [C0603]  (hidden comment: Capacitor)
C104  value 1nF  [C0603]  (hidden comment: Capacitor)
C105  value 1nF  [C0603]  (hidden comment: Capacitor)
C106  value 10pF  [C0603]  (hidden comment: Capacitor)
C107  value 100nF  [C0603]  (hidden comment: Capacitor)
C108  value 1nF  [C0603]  (hidden comment: Capacitor)
C109  value 1nF  [C0603]  (hidden comment: Capacitor)
C110  value 1nF  [C0603]  (hidden comment: Capacitor)
C111  value 1uF  [C0805_H0P85]  (hidden comment: Capacitor)
C112  value 1nF  [C0603]  (hidden comment: Capacitor)
C113  value 1uF  [C0805_H0P85]  (hidden comment: Capacitor)
C114  value 10pF  [C0603]  (hidden comment: Capacitor)
C115  value 10pF  [C0603]  (hidden comment: Capacitor)
C116  value 100nF  [C0603]  (hidden comment: Capacitor)
C117  value 100pF  [C0603]  (hidden comment: Capacitor)
C118  value 100pF  [C0603]  (hidden comment: Capacitor)
C119  value 100nF  [C0603]  (hidden comment: Capacitor)
C120  value 1nF  [C0603]  (hidden comment: Capacitor)
C121  value 1nF  [C0603]  (hidden comment: Capacitor)
C122  value 10pF  [C0603]  (hidden comment: Capacitor)
C123  value 10pF  [C0603]  (hidden comment: Capacitor)
C124  value 1nF  [C0603]  (hidden comment: Capacitor)
C125  value 1nF  [C0603]  (hidden comment: Capacitor)
CN2  Header 5x1  [CON_SAMTEC_TSW-105-07-X-S]
CN3  Header 3x1  [CON_SAMTEC_TSW-103-07-F-S]
CN4  Header 3x1  [CON_SAMTEC_TSW-103-07-F-S]
D9  value BAT54SFILM  [DIO_SOT23]  (hidden comment: DIODE_3P_DUAL_SERIES)
D10  value BAT54SFILM  [DIO_SOT23]  (hidden comment: DIODE_3P_DUAL_SERIES)
D11  value BAT54SFILM  [DIO_SOT23]  (hidden comment: DIODE_3P_DUAL_SERIES)
D12  value BAT54SFILM  [DIO_SOT23]  (hidden comment: DIODE_3P_DUAL_SERIES)
D13  value BAT54FILM  [DIO_SOT23]  (hidden comment: DIODE_SOT23)
D14  value BAT54FILM  [DIO_SOT23]  (hidden comment: DIODE_SOT23)
D15  value BAT54FILM  [DIO_SOT23]  (hidden comment: DIODE_SOT23)
D16  value BAT54SFILM  [DIO_SOT23]  (hidden comment: DIODE_3P_DUAL_SERIES)
D17  value BAT54FILM  [DIO_SOT23]  (hidden comment: DIODE_SOT23)
D18  value BAT54SFILM  [DIO_SOT23]  (hidden comment: DIODE_3P_DUAL_SERIES)
D19  value BAT54SFILM  [DIO_SOT23]  (hidden comment: DIODE_3P_DUAL_SERIES)
H1  Test Point  [TP_SMD_1MM]  (value not drawn)  (no BOM)
H2  Test Point  [TP_SMD_1MM]  (value not drawn)  (no BOM)
H3  Test Point  [TP_SMD_1MM]  (value not drawn)  (no BOM)
Icc_Current  Test_pin_conn_black - NOT CONNECTED  [TP_PTH-1P02MM_TEST-TERMINAL_RS_101-2391_BLACK]  (value not drawn)
JP10  value Header 2x1  [CON_SAMTEC_TSW-102-07-G-S]  (hidden comment: Jumper_Header 2x1)
JP11  value Header 3x1  [CON_SAMTEC_TSW-103-07-F-S]  (hidden comment: Jumper_Header 3x1 Fitted 1-2)
JP12  value Header 2x1  [CON_SAMTEC_TSW-102-07-G-S]  (hidden comment: Jumper_Header 2x1)
JP13  value Header 2x1  [CON_SAMTEC_TSW-102-07-G-S]  (hidden comment: Jumper_Header 2x1)
JP14  value Header 3x1  [CON_SAMTEC_TSW-103-07-F-S]  (hidden comment: Jumper_Header 3x1 Fitted 1-2)
JP15  value Header 2x1  [CON_SAMTEC_TSW-102-07-G-S]  (hidden comment: Jumper_Header 2x1)
JP16  value Header 2x1  [CON_SAMTEC_TSW-102-07-G-S]  (hidden comment: Jumper_Header 2x1)
OV_Vcc  Test Point  [TP_SMD_1MM]  (value not drawn)  (no BOM)
R114  value 220K  [R0603]  (hidden comment: Resistor)
R115  value 75K  [R0603]  (hidden comment: Resistor)
R116  value 10R  [R0603]  (hidden comment: Resistor)
R117  value 11K  [R0603]  (hidden comment: Resistor)
R118  value 9K31  [R0805_H0P5]  (hidden comment: Resistor)
R119  value 2K8  [R0603_H0P45]  (hidden comment: Resistor)
R120  value 169K  [R0603]  (hidden comment: Resistor)
R121  value 100R  [R0603]  (hidden comment: Resistor)
R122  value 220K  [R0603]  (hidden comment: Resistor)
R123  value 75K  [R0603]  (hidden comment: Resistor)
R124  value 10K  [R0603]  (hidden comment: Resistor)
R125  value 10K  [R0603]  (hidden comment: Resistor)
R126  value 13K  [R0603]  (hidden comment: Resistor)
R127  value 10R  [R0603]  (hidden comment: Resistor)
R128  value 220R  [R0603]  (hidden comment: Resistor)
R129  value 0R  [R0603]  (hidden comment: Resistor)
R130  value 11K  [R0603]  (hidden comment: Resistor)
R131  value 9K31  [R0805_H0P5]  (hidden comment: Resistor)
R132  value 220K  [R0603]  (hidden comment: Resistor)
R133  value 75K  [R0603]  (hidden comment: Resistor)
R134  value 10R  [R0603]  (hidden comment: Resistor)
R135  value 10K  [R0603_H0P45]  (hidden comment: Resistor)
R136  value 11K  [R0603]  (hidden comment: Resistor)
R137  value 9K31  [R0805_H0P5]  (hidden comment: Resistor)
R138  value 100R  [R0603]  (hidden comment: Resistor)
R139  value 10K  [R0603_H0P45]  (hidden comment: Resistor)
R140  value 2K2  [R0603]  (hidden comment: Resistor)
R141  value 2K2  [R0603]  (hidden comment: Resistor)
R142  value 2K2  [R0603]  (hidden comment: Resistor)
R143  value 169K  [R0603]  (hidden comment: Resistor)
R144  value 10R  [R0603]  (hidden comment: Resistor)
R145  value 10R  [R0805_H0P5]  (hidden comment: Resistor)
R146  value 10K  [R0603]  (hidden comment: Resistor)
R147  value 4K22  [R0603_H0P45]  (hidden comment: Resistor)
R148  value 4K22  [R0603_H0P45]  (hidden comment: Resistor)
R149  value 4K22  [R0603_H0P45]  (hidden comment: Resistor)
R150  value 11K  [R0603]  (hidden comment: Resistor)
R151  value 9K31  [R0805_H0P5]  (hidden comment: Resistor)
R152  value 10R  [R0603]  (hidden comment: Resistor)
R153  value 560R  [R0603]  (hidden comment: Resistor)
R154  value 10R  [R0603]  (hidden comment: Resistor)
R155  value 0R  [R0805]  (hidden comment: Resistor)
R156  value 10R  [R0603]  (hidden comment: Resistor)
R157  value 560R  [R0603]  (hidden comment: Resistor)
R158  value 10K  [R0603]  (hidden comment: Resistor)
R159  value 10R  [R0805_H0P5]  (hidden comment: Resistor)
R160  value 100R  [R0603]  (hidden comment: Resistor)
R161  value 10R  [R0805_H0P5]  (hidden comment: Resistor)
R162  value 10K  [R0603]  (hidden comment: Resistor)
R163  value 10R  [R0805_H0P5]  (hidden comment: Resistor)
R164  value 10K  [R0603]  (hidden comment: Resistor)
R165  value 10R  [R0603]  (hidden comment: Resistor)
R166  value 10R  [R0603]  (hidden comment: Resistor)
R167  value 560R  [R0603]  (hidden comment: Resistor)
R168  value 560R  [R0603]  (hidden comment: Resistor)
R169  value 10R  [R0603]  (hidden comment: Resistor)
R170  value 0R  [R0805]  (hidden comment: Resistor)
R171  value 10R  [R0603]  (hidden comment: Resistor)
R172  value 0R  [R0805]  (hidden comment: Resistor)
R173  value 10K  [R0603]  (hidden comment: Resistor)
R174  value 10R  [R0603]  (hidden comment: Resistor)
R175  value 560R  [R0603]  (hidden comment: Resistor)
R176  value 10R  [R0603]  (hidden comment: Resistor)
R177  value 560R  [R0603]  (hidden comment: Resistor)
R178  value 100R  [R0603]  (hidden comment: Resistor)
R179  value 10K  [R0603]  (hidden comment: Resistor)
R180  value 10K  [R0603]  (hidden comment: Resistor)
R181  value 10R  [R0805_H0P5]  (hidden comment: Resistor)
R182  value 10R  [R0805_H0P5]  (hidden comment: Resistor)
RV2  value 1K  [POT_BOURNS_3386P-1-101TLF]  (hidden comment: POTENTIOMETER)
ShuntU+  Test_pin_conn_black - NOT CONNECTED  [TP_PTH-1P02MM_TEST-TERMINAL_RS_101-2391_BLACK]  (value not drawn)
ShuntV+  Test_pin_conn_black - NOT CONNECTED  [TP_PTH-1P02MM_TEST-TERMINAL_RS_101-2391_BLACK]  (value not drawn)
ShuntW+  Test_pin_conn_black - NOT CONNECTED  [TP_PTH-1P02MM_TEST-TERMINAL_RS_101-2391_BLACK]  (value not drawn)
Throttle  Test Point  [TP_SMD_1MM]  (value not drawn)  (no BOM)
TP6  Test Point  [TP_SMD_1MM]  (value not drawn)  (no BOM)
U10  value TS3021ILT  [AOP_SOT23-5L_H1P45]  (hidden comment: TS3021)
U11  TSC2020IST  [ICC_MINISO8_3X3_P065]
U12  TSV911ILT  [AOP_SOT23-5L_H1P45]
U13  TSV791ILT  [ICC_SOT23-5L_H1P45]
U14  TSV791ILT  [ICC_SOT23-5L_H1P45]
U15  TSV791ILT  [ICC_SOT23-5L_H1P45]
Vcc_PW  Test_pin_conn_black - NOT CONNECTED  [TP_PTH-1P02MM_TEST-TERMINAL_RS_101-2391_BLACK]  (value not drawn)
VU  Test_pin_conn_black - NOT CONNECTED  [TP_PTH-1P02MM_TEST-TERMINAL_RS_101-2391_BLACK]  (value not drawn)
VV  Test_pin_conn_black - NOT CONNECTED  [TP_PTH-1P02MM_TEST-TERMINAL_RS_101-2391_BLACK]  (value not drawn)
VW  Test_pin_conn_black - NOT CONNECTED  [TP_PTH-1P02MM_TEST-TERMINAL_RS_101-2391_BLACK]  (value not drawn)

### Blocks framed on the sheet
Phase Voltage Sensing: C74-C76 C81 C83 C84 C87-C89 D9 D11 D12 JP10 JP13 JP15 R114-R118 R122 R123 R127 R130-R134 R136 R137 VU VV VW
Batterie Current Sensing: C78 C82 C85 Icc_Current R128 U11
External Opamp Biasing: Bias C86 C91 C92 C94 JP14 R135 R138 R139 U12
External Opamps Phase Current Sensing: C95-C98 C102 C104-C106 C108-C115 C117 C118 C120-C125 R145 R146 R152-R159 R161-R172 R174-R177 R179-R182 ShuntU+ ShuntV+ ShuntW+ U13-U15
Batterie Voltage Sensing: C99-C101 D16 JP16 R143 R144 R150 R151 Vcc_PW

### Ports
Brake_Levers (out), Hall H1 (out), Hall H2 (out), Hall H3 (out), Icc_Current (out), Icc_Power+ (in), Icc_Power- (in), IoutU+ (in), IoutU- (in), IoutV+ (in), IoutV- (in), IoutW+ (in), IoutW- (in), OV_Vcc_Power (out), Ref_Current_6S (in), ShuntU+ (out), ShuntU- (out), ShuntV+ (out), ShuntV- (out), ShuntW+ (out), ShuntW- (out), Throttle (out), Vcc_Pw (out), VoutU (in), VoutV (in), VoutW (in), VU (out), VV (out), VW (out)

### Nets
3V3_analog_power: C77.2 C78.2 C86.2 C98.2 C103.1 C111.2 C113.2 C116.1 CN3.3 CN4.3 D9.2 D10.2 D11.2 D12.2 D16.2 D18.2 D19.2 JP11.1 R114.2 R122.2 R132.2 R173.2 RV2.3(TOP) U10.5(VCC) U11.6(VCC) U11.7(VREF1) U12.5(VCC+) U13.5(Vcc+) U14.5(Vcc+) U15.5(Vcc+)
+5V_power: C90.1 D13.1(A) R140.2 R141.2 R142.2
Bias: Bias.1 C92.2 C94.2 C97.2 C114.2 C115.2 R138.2 R146.2 R162.2 R164.2 U12.4(IN-)
GND: C74.1 C75.1 C76.1 C77.1 C78.1 C79.2 C80.1 C81.1 C83.1 C84.1 C85.1 C86.1 C87.1 C88.1 C89.1 C90.2 C91.1 C92.1 C93.2 C95.2 C96.2 C98.1 C99.1 C100.1 C101.1 C102.1 C103.2 C104.2 C105.1 C107.2 C108.2 C109.2 C110.2 C111.1 C112.2 C113.1 C116.2 C117.1 C118.1 C119.2 C120.1 C121.1 C124.1 C125.1 CN2.1 CN3.1 CN4.1 D9.1 D10.1 D11.1 D12.1 D16.1 D18.1 D19.1 R117.1 R118.1 R124.1 R125.1 R129.1 R130.1 R131.1 R136.1 R137.1 R139.1 R147.1 R148.1 R149.1 R150.1 R151.1 RV2.1(BOT) U10.2(VDD) U11.2(GND) U11.3(VREF2) U11.4(NC) U12.2(VCC-) U13.2(Vcc-) U14.2(Vcc-) U15.2(Vcc-)
Vcc_power: R120.2 R143.2
Vref_pci: JP14.1
Brake_Levers: Brake_Levers.1 C119.1 D19.3 R178.2 ; port Brake_Levers
Hall H1: D14.1(A) H1.1 R140.1 R147.2 ; port Hall H1
Hall H2: D15.1(A) H2.1 R141.1 R148.2 ; port Hall H2
Hall H3: D17.1(A) H3.1 R142.1 R149.2 ; port Hall H3
Icc_Current: C85.2 Icc_Current.1 R128.2 ; port Icc_Current
Icc_Power+: C82.2 U11.8(IN+) ; port Icc_Power+
Icc_Power-: C82.1 U11.1(IN-) ; port Icc_Power-
IoutU+: R145.1 R152.1 ; port IoutU+
IoutU-: R156.1 R159.2 ; port IoutU-
IoutV+: R161.1 R165.1 ; port IoutV+
IoutV-: R174.1 R181.2 ; port IoutV-
IoutW+: R163.1 R166.1 ; port IoutW+
IoutW-: R176.1 R182.2 ; port IoutW-
OV_Vcc_Power: OV_Vcc.1 R121.2 ; port OV_Vcc_Power
Ref_Current_6S: JP14.3 ; port Ref_Current_6S
ShuntU+: C95.1 R145.2 R155.1 ShuntU+.1 ; port ShuntU+
ShuntU-: C104.1 R159.1 ; port ShuntU-
ShuntV+: C109.1 R161.2 R170.1 ShuntV+.1 ; port ShuntV+
ShuntV-: C124.2 R181.1 ; port ShuntV-
ShuntW+: C108.1 R163.2 R172.1 ShuntW+.1 ; port ShuntW+
ShuntW-: C125.2 R182.1 ; port ShuntW-
Throttle: C107.1 D18.3 R160.2 Throttle.1 ; port Throttle
Vcc_Pw: C99.2 R144.2 Vcc_PW.1 ; port Vcc_Pw
VoutU: R115.2 ; port VoutU
VoutV: R123.2 ; port VoutV
VoutW: R133.2 ; port VoutW
VU: C74.2 R116.2 VU.1 ; port VU
VV: C81.2 R127.2 VV.1 ; port VV
VW: C87.2 R134.2 VW.1 ; port VW
NetC75_2: C75.2 D9.3 JP10.1(COMMON) R114.1 R115.1 R116.1 R117.2
NetC76_2: C76.2 JP10.2(NO) R118.2
NetC79_1: C79.1 R119.1 R126.2 TP6.1 U10.4(IN-)
NetC80_2: C80.2 D10.3 JP12.1(COMMON) R120.1 R124.2 U10.3(IN+)
NetC83_2: C83.2 D11.3 JP13.1(COMMON) R122.1 R123.1 R127.1 R130.2
NetC84_2: C84.2 JP13.2(NO) R131.2
NetC88_2: C88.2 D12.3 JP15.1(COMMON) R132.1 R133.1 R134.1 R136.2
NetC89_2: C89.2 JP15.2(NO) R137.2
NetC91_2: C91.2 R135.1 R139.2 U12.3(IN+)
NetC93_1: C93.1 CN2.5 D13.3(K)
NetC94_1: C94.1 R138.1 U12.1(NC)
NetC96_1: C96.1 R152.2 R153.1
NetC97_1: C97.1 R146.1 R153.2 U13.3
NetC100_2: C100.2 D16.3 JP16.1(COMMON) R143.1 R144.1 R150.2
NetC101_2: C101.2 JP16.2(NO) R151.2
NetC102_2: C102.2 R154.2 R155.2
NetC105_2: C105.2 R156.2 R157.1
NetC106_1: C106.1 R154.1 R158.2 U13.1(NC)
NetC106_2: C106.2 R157.2 R158.1 U13.4
NetC110_1: C110.1 R165.2 R167.1
NetC112_1: C112.1 R166.2 R168.1
NetC114_1: C114.1 R162.1 R167.2 U14.3
NetC115_1: C115.1 R164.1 R168.2 U15.3
NetC117_2: C117.2 R169.2 R170.2
NetC118_2: C118.2 R171.2 R172.2
NetC120_2: C120.2 R174.2 R175.1
NetC121_2: C121.2 R176.2 R177.1
NetC122_1: C122.1 R169.1 R179.2 U14.1(NC)
NetC122_2: C122.2 R175.2 R179.1 U14.4
NetC123_1: C123.1 R171.1 R180.2 U15.1(NC)
NetC123_2: C123.2 R177.2 R180.1 U15.4
NetCN2_2: CN2.2 D17.3(K)
NetCN2_3: CN2.3 D15.3(K)
NetCN2_4: CN2.4 D14.3(K)
NetCN3_2: CN3.2 R160.1
NetCN4_2: CN4.2 R173.1 R178.1
NetJP11_2: JP11.2 R119.2
NetJP11_3: JP11.3 RV2.2(TAP)
NetJP12_2: JP12.2(NO) R125.2
NetJP14_2: JP14.2 R135.2
NetR121_1: R121.1 U10.1(OUT)
NetR126_1: R126.1 R129.2
NetR128_1: R128.1 U11.5(OUT)

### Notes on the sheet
- Icc_Current = 1.65V + 20 x RPW x IVbat
- Jumper :
  1-2 -> Fixed Overvoltage
  2-3 -> Variable Overvoltage
- Jumper :
  1-2 -> Bias = Vref_pci / 2 (1.65V)
  2-3 -> Bias = Ref_Current_6S / 2
- Jumpers :
  Not fitted -> Vbat <= 24V, Ratio = 0.128, for VX outputs, -3dB cut-off frequency = 502Hz
  Fitted -> Vbat <= 48V, Ratio = 0.063, for VX outputs, -3dB cut-off frequency = 510Hz
- Jumper JP12 :
  Not fitted -> Vbat <= 24V
  Overvoltage = 48.5V
  Fitted -> Vbat <= 48V
  Overvoltage = 94.4V
  Fitted -> Vbat <= 24V
  Overvoltage = 94.4V
- Overvoltage Detection
- Hall Sensors
- Jumpers :
  Not fitted -> Vbat <= 24V, Ratio = 0.061
  Fitted -> Vbat <= 48V, Ratio = 0.029
- Throttle bicycle
- Brake Levers
- Shuntx+ = Bias +/- (10k/570) x RSx x ImotorX
  JP14 on Vref_pci gives Shuntx+ =  1.65V +/- (10k/570) x RSx x ImotorX

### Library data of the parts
Bias Brake_Levers H1-H3 OV_Vcc Throttle TP6 = MCD-00074: as GHU on sheet Power_Stage
C74 C81 C87 C99 C102 C117 C118 = MCD-01101: Capacitor, MLCC, 100pF, 50V, X7R, +/-5%, 0603, T=0.33mm; Part_Preference: Recommended; Manufacturer: AVX; Manufacturer_Part_Number: 06035C101JAT4A; Component_Country_Of_Origin: China; ShowFields: YES; ID: 3399
C75 C76 C83 C84 C88 C89 = MCD-01052: Capacitor, MLCC, 33nF, 50V, X7R, +/-5%, 0603, T=1.25mm; Part_Preference: Recommended; Manufacturer: AVX; Manufacturer_Part_Number: 06035C333JAT2A; Order_Code_RS: 134-9694; Component_Country_Of_Origin: China; ShowFields: YES; ID: 2971
C77 C78 C86 C91 C92 C98 C111 C113 = MCD-01550: Capacitor, MLCC, 1uF, 16V, X5R, +/-10%, 0805, T=0.85mm; Part_Preference: Recommended; Manufacturer: YAGEO; Manufacturer_Part_Number: CC0805KRX5R7BB105; Component_Country_Of_Origin: China; ShowFields: YES; ID: 3650
C79 C90 C93 C103 C107 C116 C119 = MCD-01099: as C44 on sheet Power_Stage
C80 C95 C96 C104 C105 C108-C110 C112 C120 C121 C124 C125 = MCD-01091: Capacitor, MLCC, 1nF, 100V, X7R, +/-10%, 0603, T=0.8mm; Part_Preference: Recommended; Manufacturer: YAGEO; Manufacturer_Part_Number: CC0603KRX7R0BB102; Order_Code_RS: 669-9000; Component_Country_Of_Origin: China; ShowFields: YES; ID: 3403
C82 C85 C94 C100 C101 = MCD-01098: Capacitor, MLCC, 10nF, 100V, X7R, +/-10%, 0603, T=0.8mm; Part_Preference: Recommended; Manufacturer: YAGEO; Manufacturer_Part_Number: CC0603KRX7R0BB103; Component_Country_Of_Origin: China; ShowFields: YES; ID: 3396
C97 C106 C114 C115 C122 C123 = MCD-00637: Capacitor, MLCC, 10pF, 50V, NPO, +/-5%, 0603, T=0.8mm; Part_Preference: Recommended; Manufacturer: YAGEO; Manufacturer_Part_Number: CC0603JRNPO9BN100; Order_Code_RS: 616-9054; Component_Country_Of_Origin: China; ShowFields: YES; ID: 3104
CN2 = MCD-02060: Header, 5x1, 2.54mm, VR, TH, T=5.84mm/2.54mm; Part_Type: Connector; Part_Preference: Recommended; Manufacturer: SAMTEC; Manufacturer_Part_Number: TSW-105-07-G-S; Order_Code_RS: 161-2268; Component_Country_Of_Origin: China, Costa Rica, Malaysia, USA, Vietnam; ShowFields: YES; ID: 4160
CN3 CN4 = MCD-02272: Header, 3x1, 2,54mm, VR, TH, T= 5.84mm/2.54mm; Part_Type: Connector; Part_Preference: Recommended; Manufacturer: SAMTEC; Manufacturer_Part_Number: TSW-103-07-F-S; Component_Country_Of_Origin: China, Costa Rica, Malaysia, USA, Vietnam; ShowFields: YES; ID: 4372
D9-D12 D16 D18 D19 = MCD-03277: Diode, Schottky, 0V3, 300mA, 40V, SOT-23; Part_Preference: Recommended; Manufacturer: STMICROELECTRONICS; Order_Code_RS: 714-6863; Component_Country_Of_Origin: China; ShowFields: YES; ID: 5393
D13-D15 D17 = MCD-03281: Diode, Schottky, Single, 0V3, 300mA, 40V, SOT-23; Part_Preference: Recommended; Manufacturer: STMICROELECTRONICS; Order_Code_RS: 714-6866; Component_Country_Of_Origin: China; ShowFields: YES; ID: 5397
Icc_Current ShuntU+ ShuntV+ ShuntW+ Vcc_PW VU VV VW = MCD-00713: as HinU on sheet Power_Stage
JP10 JP12 JP13 JP15 JP16 = MCD-00045: as JP9 on sheet Power_Stage
JP11 JP14 = MCD-01905: as JP5-JP8 on sheet Power_Stage
R114 R122 R132 = MCD-00347: Resistor, 220K, 0603, +/-1%, 1/10W; Part_Preference: Recommended; Manufacturer: YAGEO; Manufacturer_Part_Number: RC0603FR-07220KL; Component_Country_Of_Origin: China; ShowFields: YES; ID: 2930
R115 R123 R133 = MCD-00522: Resistor, 75K, 0603, +/-1%, 1/10W; Part_Preference: Recommended; Manufacturer: YAGEO; Manufacturer_Part_Number: RC0603FR-0775KL; Component_Country_Of_Origin: China; ShowFields: YES; ID: 3221
R116 R127 R134 R144 R152 R154 R156 R165 R166 R169 R171 R174 R176 = MCD-00186: Resistor, 10R, 0603, +/-1%, 1/10W; BMS_Part_Number: 9129019; Part_Preference: Recommended; Manufacturer: YAGEO; Manufacturer_Part_Number: RC0603FR-0710RL; Component_Country_Of_Origin: China; ShowFields: YES; ID: 2679
R117 R130 R136 R150 = MCD-00366: Resistor, 11K, 0603, +/-1%, 1/10W; Part_Preference: Recommended; Manufacturer: YAGEO; Manufacturer_Part_Number: RC0603FR-0711KL; Component_Country_Of_Origin: China; ShowFields: YES; ID: 2910
R118 R131 R137 R151 = MCD-03670: Resistor, 9K31, 0805, +/-1%, 1/8W; Part_Preference: Recommended; Manufacturer: YAGEO; Manufacturer_Part_Number: RC0805FR-079K31L; Component_Country_Of_Origin: China; ShowFields: YES; ID: 5786
R119 = MCD-02176: Resistor, 2K8, 0603, +/-0.1%, 1/10W, +/-50ppm/°C; Part_Preference: Recommended; Manufacturer: YAGEO; Manufacturer_Part_Number: RT0603BRE072K8L; Component_Country_Of_Origin: China; ShowFields: YES; ID: 4276
R120 R143 = MCD-02183: Resistor, 169K, 0603, +/-1%, 1/10W; Part_Preference: Recommended; Manufacturer: YAGEO; Manufacturer_Part_Number: RC0603FR-07169KL; Component_Country_Of_Origin: China; ShowFields: YES; ID: 4283
R121 R138 R160 R178 = MCD-00224: as R68 on sheet Power_Stage
R124 R125 R146 R158 R162 R164 R173 R179 R180 = MCD-00220: Resistor, 10K, 0603, +/-1%, 1/10W; Part_Preference: Recommended; Manufacturer: YAGEO; Manufacturer_Part_Number: RC0603FR-0710KL; Component_Country_Of_Origin: China; ShowFields: YES; ID: 2649
R126 = MCD-00384: as R110 on sheet Power_Stage
R128 = MCD-00428: Resistor, 220R, 0603, +/-1%, 1/10W; BMS_Part_Number: 9129728; Part_Preference: Recommended; Manufacturer: YAGEO; Manufacturer_Part_Number: RC0603FR-07220RL; Component_Country_Of_Origin: China; ShowFields: YES; ID: 2851
R129 = MCD-00056: Resistor, 0R, 0603, +/-5%, 1/10W; Part_Preference: Recommended; Manufacturer: YAGEO; Manufacturer_Part_Number: RC0603JR-070RL; Order_Code_RS: 9233130RL; Component_Country_Of_Origin: China; ShowFields: YES; ID: 2536
R135 R139 = MCD-01566: Resistor, 10K, 0603, +/-0.1%, 1/10W, +/-50ppm/°C; Part_Preference: Recommended; Manufacturer: YAGEO; Manufacturer_Part_Number: RT0603BRE0710KL; Partial_Alternate_Internal_Part_Number: MCD-01669; Component_Country_Of_Origin: China; ShowFields: YES; ID: 3666
R140-R142 = MCD-00349: Resistor, 2K2, 0603, +/-1%,1/10W; Part_Preference: Recommended; Manufacturer: YAGEO; Manufacturer_Part_Number: RC0603FR-072K2L; Component_Country_Of_Origin: China; ShowFields: YES; ID: 2929
R145 R159 R161 R163 R181 R182 = MCD-01548: Resistor, 10R, 0805, +/-1%, 1/8W; BMS_Part_Number: 9129303; Part_Preference: Recommended; Manufacturer: YAGEO; Manufacturer_Part_Number: RC0805FR-0710RL; Order_Code_RS: 618-5179; Component_Country_Of_Origin: China; ShowFields: YES; ID: 3648
R147-R149 = MCD-01571: Resistor, 4K22, 0603, +/-1%, 1/10W; Part_Preference: Recommended; Manufacturer: YAGEO; Manufacturer_Part_Number: RC0603FR-074K22L; Component_Country_Of_Origin: China; ShowFields: YES; ID: 3671
R153 R157 R167 R168 R175 R177 = MCD-00490: Resistor, 560R, 0603, +/-1%, 1/10W; BMS_Part_Number: 9129742; Part_Preference: Recommended; Manufacturer: YAGEO; Manufacturer_Part_Number: RC0603FR-07560RL; Component_Country_Of_Origin: China; ShowFields: YES; ID: 2787
R155 R170 R172 = MCD-00179: Resistor, 0R, 0805, +/-5%, 1/8W; Part_Preference: Recommended; Manufacturer: YAGEO; Manufacturer_Part_Number: RC0805JR-070RL; Component_Country_Of_Origin: China; ShowFields: YES; ID: 2685
RV2 = MCD-02050: as RV1 on sheet Power_Stage
U10 = MCD-02179: Comparator, 1V8, Rail-to-rail, high-speed; Part_Type: IC; Part_Preference: Recommended; Manufacturer: STMICROELECTRONICS; Manufacturer_HQ_COO: EU; Component_Country_Of_Origin: China; ShowFields: YES; ID: 4279
U11 = MCD-04028: Differential Current-Sense Amplifier, 650KHz Bandwidth, -4V To 100V, Gain 20V/V, 5V; Part_Type: IC; Part_Preference: Recommended; Manufacturer: STMICROELECTRONICS; Component_Country_Of_Origin: China; ShowFields: YES; ID: 6144
U12 = MCD-01192: Operational Amplifier, Single/dual/quad rail-to-rail input/output, 5V5, 8MHz; BMS_Part_Number: 9177436; Part_Type: IC; Part_Preference: Recommended; Manufacturer: STMICROELECTRONICS; Manufacturer_HQ_COO: EU; Order_Code_RS: 179-092; Component_Country_Of_Origin: China; ShowFields: YES; ID: 3305
U13-U15 = MCD-03445: Single Op-amp, High bandwidth 50 MHz, low offset 200uV, rail-to-rail, 5V; Part_Type: IC; Part_Preference: Recommended; Manufacturer: STMICROELECTRONICS; Order_Code_RS: 3864642; ShowFields: YES; ID: 5561; Component_Country_Of_Origin: Malaysia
